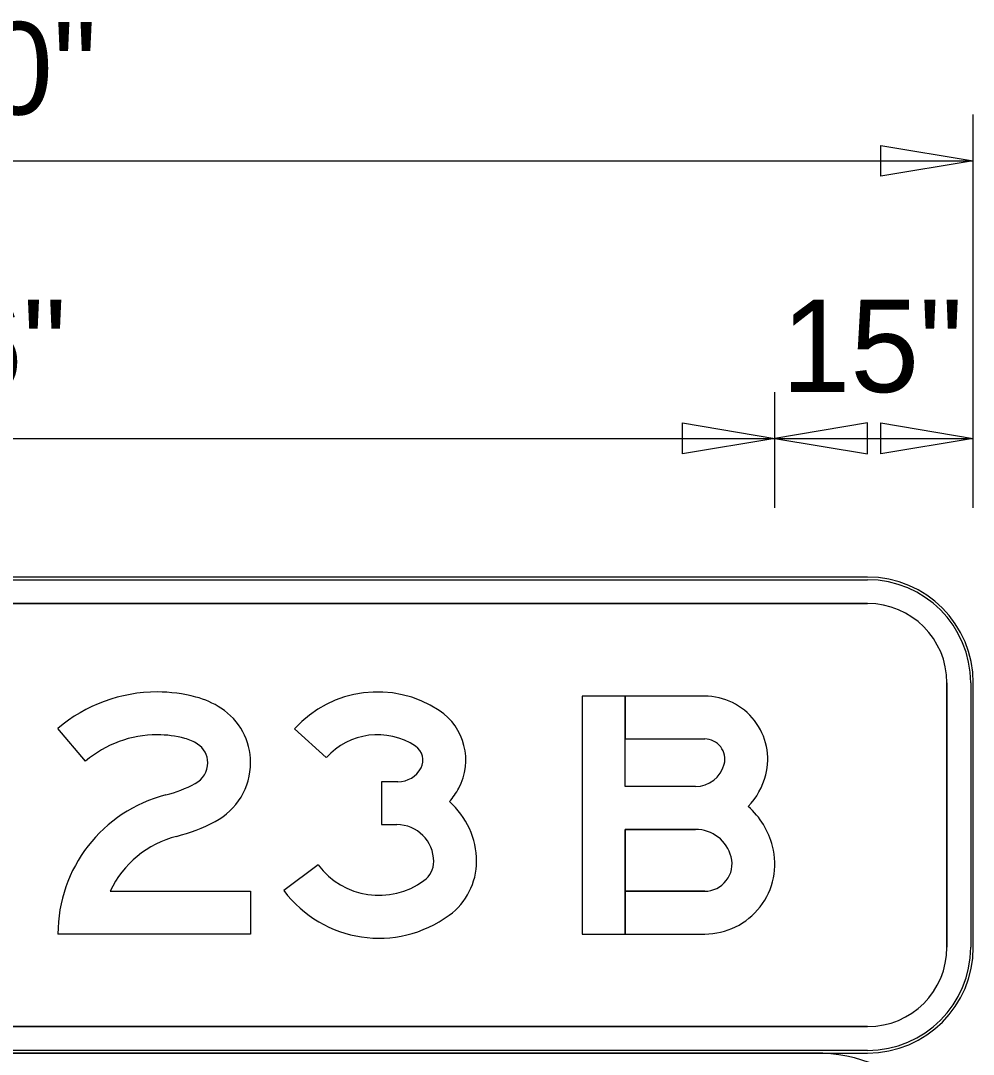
# Model space of a CAD drawing. Extents: x 2149961 to 2150220, y 145114 to 145240.
# Drawn here: x 2150041.01 to 2150047.02, y 145154.62 to 145161.14 of the extents above; entities that cross this region are included whole.
import ezdxf

# ---------------------------------------------------------------- set-up
doc = ezdxf.new("R2010")
doc.units = 0
for name, color, linetype in [('GSBWFILL', 7, 'Continuous'), ('GSCOLORFILL', 7, 'Continuous'), ('GSDIMS', 7, 'Continuous'), ('GSOUTLINE', 7, 'Continuous')]:
    doc.layers.add(name, color=color, linetype=linetype)

msp = doc.modelspace()

# ---------------------------------------------------------------- linework, layer by layer
at = {"layer": 'GSBWFILL'}
for p, q in [((2150046.3534, 145157.6336), (2150034.6865, 145157.6336)), ((2150034.6865, 145157.4669), (2150046.3534, 145157.4669)), ((2150046.8534, 145156.9669), (2150046.8534, 145155.2996)), ((2150047.0201, 145155.2996), (2150047.0201, 145156.9669)), ((2150042.7392, 145156.677), (2150042.9395, 145156.496)), ((2150042.8877, 145155.819), (2150042.6717, 145155.657)), ((2150046.3534, 145154.7996), (2150034.6881, 145154.7996)), ((2150046.02, 145154.6329), (2150032.52, 145154.6329)), ((2150034.6881, 145154.6329), (2150046.3534, 145154.6329))]:
    msp.add_line(p, q, dxfattribs=at)
for points in [[(2150045.2677, 145156.3132), (2150044.8233, 145156.3132), (2150044.8233, 145156.8832), (2150044.5533, 145156.8832), (2150044.5533, 145155.3832), (2150044.8233, 145155.3832)], [(2150045.3258, 145156.8832), (2150044.8234, 145156.8832), (2150044.8234, 145156.6132), (2150045.3258, 145156.6132)], [(2150041.4214, 145156.4737), (2150041.2467, 145156.6795)], [(2150043.3913, 145156.3432), (2150043.2867, 145156.3432), (2150043.2867, 145156.0732), (2150043.3842, 145156.0732)], [(2150044.8233, 145155.3832), (2150044.8233, 145156.0432), (2150045.2677, 145156.0432)], [(2150041.5769, 145155.6532), (2150042.4617, 145155.6532), (2150042.4617, 145155.3832), (2150041.2467, 145155.3832)], [(2150045.3258, 145155.6532), (2150044.8234, 145155.6532), (2150044.8234, 145155.3832), (2150045.3258, 145155.3832)]]:
    msp.add_lwpolyline(points, dxfattribs=at)
for centre, radius, start, end in [((2150046.3534, 145156.9669), 0.6667, 0, 90), ((2150046.3534, 145156.9669), 0.5, 0, 90), ((2150041.8729, 145155.9416), 0.9678, 90, 130.32246), ((2150041.8729, 145155.9613), 0.9482, 75.09879, 90), ((2150043.2624, 145156.2045), 0.705, 56.57666, 137.91651), ((2150041.9753, 145156.3459), 0.5501, 56.98303, 75.09879), ((2150042.0517, 145156.4635), 0.41, 0, 56.98303), ((2150043.4442, 145156.4799), 0.375, 331.83123, 56.57666), ((2150041.8729, 145155.9416), 0.6978, 90, 130.32246), ((2150041.8729, 145155.9613), 0.6782, 75.09879, 90), ((2150043.2624, 145156.2045), 0.435, 56.57666, 137.91651), ((2150041.9753, 145156.3459), 0.2801, 56.98303, 75.09879), ((2150042.0517, 145156.4635), 0.14, 0, 56.98303), ((2150043.4442, 145156.4799), 0.105, 331.83123, 56.57666), ((2150042.0425, 145156.4635), 0.1491, 297.77324, 360), ((2150042.0425, 145156.4635), 0.4191, 297.77324, 0), ((2150043.3913, 145156.5082), 0.165, 270, 331.83123), ((2150041.7182, 145157.0793), 0.8451, 284.35432, 297.77324), ((2150042.1523, 145155.3832), 0.9056, 104.35432, 180), ((2150043.3913, 145156.5082), 0.435, 318.21804, 331.83123), ((2150043.3842, 145155.8407), 0.5025, 0.01834, 48.72597), ((2150041.7182, 145157.0793), 1.1151, 284.35432, 297.77324), ((2150043.3842, 145155.8407), 0.2325, 0.01834, 90), ((2150042.1523, 145155.3832), 0.6356, 104.35432, 154.86215), ((2150043.2717, 145156.107), 0.48, 216.8699, 306.22155), ((2150043.4667, 145155.8407), 0.15, 306.22155, 0.01834), ((2150043.4667, 145155.8407), 0.42, 306.22155, 0.01834), ((2150043.2717, 145156.107), 0.75, 216.8699, 306.22155), ((2150046.3534, 145155.2996), 0.6667, 270, 0), ((2150046.3534, 145155.2996), 0.5, 270, 0), ((2150046.02, 145153.6329), 1, 0, 90)]:
    msp.add_arc(centre, radius, start, end, dxfattribs=at)
for centre, major_axis, start_param, end_param in [((2150045.3258, 145156.4857), (0, 0.3975), 4.459709, 6.283185), ((2150045.3258, 145156.4857), (0, 0.1275), 4.459709, 6.283185), ((2150045.2677, 145156.5007), (0, 0.1875), 3.141593, 4.459709), ((2150045.2677, 145156.5007), (0, 0.4575), 3.95686, 4.459709), ((2150045.2677, 145155.8107), (0, 0.5025), 4.965069, 5.558736), ((2150045.2677, 145155.8107), (0, 0.2325), 4.965069, 6.283185), ((2150045.3258, 145155.8257), (0, 0.4425), 3.141593, 4.965069), ((2150045.3258, 145155.8257), (0, 0.1725), 3.141593, 4.965069)]:
    msp.add_ellipse(centre, major_axis=major_axis, ratio=0.999996, start_param=start_param, end_param=end_param, dxfattribs=at)
at = {"layer": 'GSCOLORFILL'}
for p, q in [((2150046.3534, 145157.6336), (2150034.6865, 145157.6336)), ((2150046.3534, 145157.6336), (2150034.6865, 145157.6336)), ((2150046.3534, 145157.6336), (2150034.6865, 145157.6336)), ((2150034.6865, 145157.6169), (2150046.3534, 145157.6169)), ((2150034.6865, 145157.4669), (2150046.3534, 145157.4669)), ((2150046.8534, 145156.9669), (2150046.8534, 145155.2996)), ((2150047.0034, 145156.9669), (2150047.0034, 145155.2996)), ((2150047.0201, 145155.2996), (2150047.0201, 145156.9669)), ((2150047.0201, 145155.2996), (2150047.0201, 145156.9669)), ((2150047.0201, 145155.2996), (2150047.0201, 145156.9669)), ((2150042.7392, 145156.677), (2150042.9395, 145156.496)), ((2150042.8877, 145155.819), (2150042.6717, 145155.657)), ((2150046.3534, 145154.7996), (2150034.6881, 145154.7996)), ((2150046.02, 145154.6329), (2150032.52, 145154.6329)), ((2150046.02, 145154.6329), (2150032.52, 145154.6329)), ((2150046.02, 145154.6329), (2150032.52, 145154.6329)), ((2150034.6865, 145154.6329), (2150046.3534, 145154.6329)), ((2150046.3534, 145154.6496), (2150034.6866, 145154.6496)), ((2150034.6866, 145154.6329), (2150046.3534, 145154.6329)), ((2150034.6881, 145154.6329), (2150046.3534, 145154.6329))]:
    msp.add_line(p, q, dxfattribs=at)
for points in [[(2150045.2677, 145156.3132), (2150044.8233, 145156.3132), (2150044.8233, 145156.8832), (2150044.5533, 145156.8832), (2150044.5533, 145155.3832), (2150044.8233, 145155.3832)], [(2150045.3258, 145156.8832), (2150044.8234, 145156.8832), (2150044.8234, 145156.6132), (2150045.3258, 145156.6132)], [(2150041.4214, 145156.4737), (2150041.2467, 145156.6795)], [(2150043.3913, 145156.3432), (2150043.2867, 145156.3432), (2150043.2867, 145156.0732), (2150043.3842, 145156.0732)], [(2150044.8233, 145155.3832), (2150044.8233, 145156.0432), (2150045.2677, 145156.0432)], [(2150041.5769, 145155.6532), (2150042.4617, 145155.6532), (2150042.4617, 145155.3832), (2150041.2467, 145155.3832)], [(2150045.3258, 145155.6532), (2150044.8234, 145155.6532), (2150044.8234, 145155.3832), (2150045.3258, 145155.3832)]]:
    msp.add_lwpolyline(points, dxfattribs=at)
for centre, radius, start, end in [((2150046.3534, 145156.9669), 0.6667, 0, 90), ((2150046.3534, 145156.9669), 0.6667, 0, 90), ((2150046.3534, 145156.9669), 0.6667, 0, 90), ((2150046.3534, 145156.9669), 0.65, 0, 90), ((2150046.3534, 145156.9669), 0.5, 0, 90), ((2150041.8729, 145155.9416), 0.9678, 90, 130.32246), ((2150041.8729, 145155.9613), 0.9482, 75.09879, 90), ((2150043.2624, 145156.2045), 0.705, 56.57666, 137.91651), ((2150041.9753, 145156.3459), 0.5501, 56.98303, 75.09879), ((2150042.0517, 145156.4635), 0.41, 0, 56.98303), ((2150043.4442, 145156.4799), 0.375, 331.83123, 56.57666), ((2150041.8729, 145155.9416), 0.6978, 90, 130.32246), ((2150041.8729, 145155.9613), 0.6782, 75.09879, 90), ((2150043.2624, 145156.2045), 0.435, 56.57666, 137.91651), ((2150041.9753, 145156.3459), 0.2801, 56.98303, 75.09879), ((2150042.0517, 145156.4635), 0.14, 0, 56.98303), ((2150043.4442, 145156.4799), 0.105, 331.83123, 56.57666), ((2150042.0425, 145156.4635), 0.1491, 297.77324, 360), ((2150042.0425, 145156.4635), 0.4191, 297.77324, 0), ((2150043.3913, 145156.5082), 0.165, 270, 331.83123), ((2150041.7182, 145157.0793), 0.8451, 284.35432, 297.77324), ((2150042.1523, 145155.3832), 0.9056, 104.35432, 180), ((2150043.3913, 145156.5082), 0.435, 318.21804, 331.83123), ((2150043.3842, 145155.8407), 0.5025, 0.01834, 48.72597), ((2150041.7182, 145157.0793), 1.1151, 284.35432, 297.77324), ((2150043.3842, 145155.8407), 0.2325, 0.01834, 90), ((2150042.1523, 145155.3832), 0.6356, 104.35432, 154.86215), ((2150043.2717, 145156.107), 0.48, 216.8699, 306.22155), ((2150043.4667, 145155.8407), 0.15, 306.22155, 0.01834), ((2150043.4667, 145155.8407), 0.42, 306.22155, 0.01834), ((2150043.2717, 145156.107), 0.75, 216.8699, 306.22155), ((2150046.3534, 145155.2996), 0.6667, 270, 0), ((2150046.3534, 145155.2996), 0.6667, 270, 0), ((2150046.3534, 145155.2996), 0.5, 270, 0), ((2150046.3534, 145155.2996), 0.6667, 270, 0), ((2150046.3534, 145155.2996), 0.65, 270, 0), ((2150046.02, 145153.6329), 1, 0, 90), ((2150046.02, 145153.6329), 1, 0, 90), ((2150046.02, 145153.6329), 1, 0, 90)]:
    msp.add_arc(centre, radius, start, end, dxfattribs=at)
for centre, major_axis, start_param, end_param in [((2150045.3258, 145156.4857), (0, 0.3975), 4.459709, 6.283185), ((2150045.3258, 145156.4857), (0, 0.1275), 4.459709, 6.283185), ((2150045.2677, 145156.5007), (0, 0.1875), 3.141593, 4.459709), ((2150045.2677, 145156.5007), (0, 0.4575), 3.95686, 4.459709), ((2150045.2677, 145155.8107), (0, 0.5025), 4.965069, 5.558736), ((2150045.2677, 145155.8107), (0, 0.2325), 4.965069, 6.283185), ((2150045.3258, 145155.8257), (0, 0.4425), 3.141593, 4.965069), ((2150045.3258, 145155.8257), (0, 0.1725), 3.141593, 4.965069)]:
    msp.add_ellipse(centre, major_axis=major_axis, ratio=0.999996, start_param=start_param, end_param=end_param, dxfattribs=at)
at = {"layer": 'GSDIMS'}
for p, q in [((2150047.0201, 145159.8211), (2150047.0201, 145160.5503)), ((2150034.0197, 145160.2586), (2150047.0201, 145160.2586)), ((2150047.0201, 145158.0711), (2150047.0201, 145159.8211)), ((2150045.7684, 145158.0711), (2150045.7684, 145158.8003)), ((2150045.7684, 145158.0711), (2150045.7684, 145158.8003)), ((2150047.0201, 145158.0711), (2150047.0201, 145158.8003)), ((2150035.2698, 145158.5086), (2150045.7684, 145158.5086)), ((2150045.7684, 145158.5086), (2150047.0201, 145158.5086))]:
    msp.add_line(p, q, dxfattribs=at)
for points in [[(2150047.0201, 145160.2586), (2150046.4368, 145160.1614), (2150046.4368, 145160.3558)], [(2150045.7684, 145158.5086), (2150045.1851, 145158.4114), (2150045.1851, 145158.6058)], [(2150045.7684, 145158.5086), (2150046.3517, 145158.4114), (2150046.3517, 145158.6058)], [(2150047.0201, 145158.5086), (2150046.4368, 145158.4114), (2150046.4368, 145158.6058)]]:
    msp.add_lwpolyline(points, close=True, dxfattribs=at)
at = {"layer": 'GSOUTLINE'}
for p, q in [((2150046.3534, 145157.6336), (2150034.6865, 145157.6336)), ((2150046.3534, 145157.4669), (2150034.6865, 145157.4669)), ((2150046.8534, 145155.2996), (2150046.8534, 145156.9669)), ((2150047.0201, 145155.2996), (2150047.0201, 145156.9669)), ((2150042.7392, 145156.677), (2150042.9395, 145156.496)), ((2150042.8877, 145155.819), (2150042.6717, 145155.657)), ((2150044.5533, 145155.3832), (2150045.3258, 145155.3832)), ((2150034.6865, 145154.7996), (2150046.3534, 145154.7996)), ((2150046.02, 145154.6329), (2150032.52, 145154.6329)), ((2150034.6865, 145154.6329), (2150046.3534, 145154.6329))]:
    msp.add_line(p, q, dxfattribs=at)
for points in [[(2150045.3258, 145156.8832), (2150044.5533, 145156.8832), (2150044.5533, 145155.3832)], [(2150041.4214, 145156.4737), (2150041.2467, 145156.6795)], [(2150045.2677, 145156.3132), (2150044.8233, 145156.3132), (2150044.8233, 145156.6132), (2150045.3258, 145156.6132)], [(2150043.3913, 145156.3432), (2150043.2867, 145156.3432), (2150043.2867, 145156.0732), (2150043.3842, 145156.0732)], [(2150045.2677, 145156.0432), (2150044.8233, 145156.0432), (2150044.8233, 145155.6532), (2150045.3258, 145155.6532)], [(2150041.5769, 145155.6532), (2150042.4617, 145155.6532), (2150042.4617, 145155.3832), (2150041.2467, 145155.3832)]]:
    msp.add_lwpolyline(points, dxfattribs=at)
for centre, radius, start, end in [((2150046.3534, 145156.9669), 0.6667, 0, 90), ((2150046.3534, 145156.9669), 0.5, 0, 90), ((2150041.8729, 145155.9416), 0.9678, 90, 130.32246), ((2150041.8729, 145155.9613), 0.9482, 75.09879, 90), ((2150043.2624, 145156.2045), 0.705, 56.57666, 137.91651), ((2150041.9753, 145156.3459), 0.5501, 56.98303, 75.09879), ((2150042.0517, 145156.4635), 0.41, 0, 56.98303), ((2150043.4442, 145156.4799), 0.375, 331.83123, 56.57666), ((2150041.8729, 145155.9416), 0.6978, 90, 130.32246), ((2150041.8729, 145155.9613), 0.6782, 75.09879, 90), ((2150043.2624, 145156.2045), 0.435, 56.57666, 137.91651), ((2150041.9753, 145156.3459), 0.2801, 56.98303, 75.09879), ((2150042.0517, 145156.4635), 0.14, 0, 56.98303), ((2150043.4442, 145156.4799), 0.105, 331.83123, 56.57666), ((2150042.0425, 145156.4635), 0.1491, 297.77324, 0), ((2150042.0425, 145156.4635), 0.4191, 297.77324, 0), ((2150043.3913, 145156.5082), 0.165, 270, 331.83123), ((2150041.7182, 145157.0793), 0.8451, 284.35432, 297.77324), ((2150042.1523, 145155.3832), 0.9056, 104.35432, 180), ((2150043.3913, 145156.5082), 0.435, 318.21804, 331.83123), ((2150043.3842, 145155.8407), 0.5025, 0.01834, 48.72597), ((2150041.7182, 145157.0793), 1.1151, 284.35432, 297.77324), ((2150043.3842, 145155.8407), 0.2325, 0.01834, 90), ((2150042.1523, 145155.3832), 0.6356, 104.35432, 154.86215), ((2150043.2717, 145156.107), 0.48, 216.8699, 306.22155), ((2150043.4667, 145155.8407), 0.15, 306.22155, 0.01834), ((2150043.4667, 145155.8407), 0.42, 306.22155, 0.01834), ((2150043.2717, 145156.107), 0.75, 216.8699, 306.22155), ((2150046.3534, 145155.2996), 0.6667, 270, 0), ((2150046.3534, 145155.2996), 0.5, 270, 0), ((2150046.02, 145153.6329), 1, 0, 90)]:
    msp.add_arc(centre, radius, start, end, dxfattribs=at)
for centre, major_axis, start_param, end_param in [((2150045.3258, 145156.4857), (0, 0.3975), 4.459709, 6.283185), ((2150045.3258, 145156.4857), (0, 0.1275), 4.459709, 6.283185), ((2150045.2677, 145156.5007), (0, 0.1875), 3.141593, 4.459709), ((2150045.2677, 145156.5007), (0, 0.4575), 3.95686, 4.459709), ((2150045.2677, 145155.8107), (0, 0.5025), 4.965069, 5.558736), ((2150045.2677, 145155.8107), (0, 0.2325), 4.965069, 6.283185), ((2150045.3258, 145155.8257), (0, 0.4425), 3.141593, 4.965069), ((2150045.3258, 145155.8257), (0, 0.1725), 3.141593, 4.965069)]:
    msp.add_ellipse(centre, major_axis=major_axis, ratio=0.999996, start_param=start_param, end_param=end_param, dxfattribs=at)

# ---------------------------------------------------------------- texts
at = {"layer": 'GSDIMS'}
for s, p in [('13\'-0"', (2150039.5056, 145160.5503)), ('126"', (2150039.7228, 145158.8003)), ('15"', (2150045.8104, 145158.8003))]:
    msp.add_text(s, height=0.58333, dxfattribs=at).set_placement(p)

doc.saveas('drawing.dxf')
